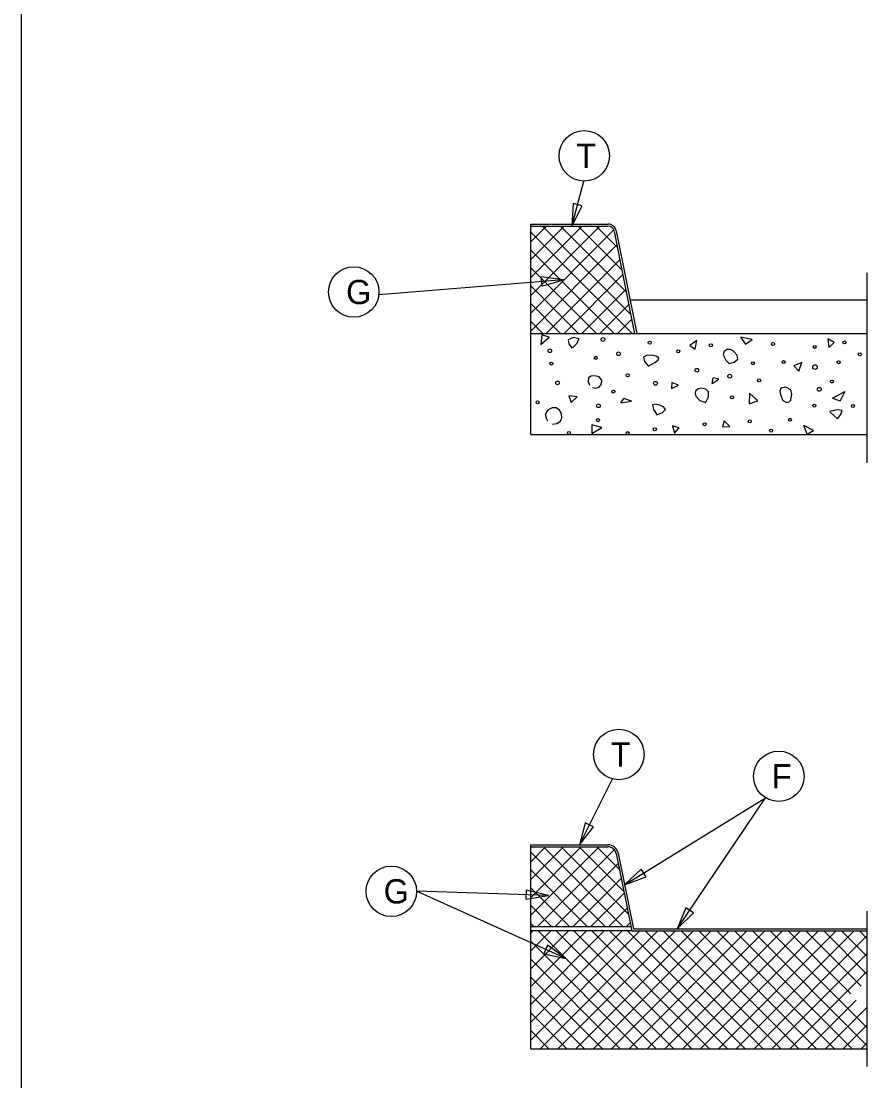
# Model space of a CAD drawing. Extents: x -439.1 to -407.9, y -458.1 to -436.2.
# Drawn here: x -439.11 to -433.87, y -452.49 to -445.93 of the extents above; entities that cross this region are included whole.
import ezdxf

# ---------------------------------------------------------------- set-up
doc = ezdxf.new("R2010")
doc.units = 0
doc.layers.add('Draft_Named_Boundary', color=7, linetype='Continuous')
doc.layers.add('Level 4', color=7, linetype='Continuous')

msp = doc.modelspace()

# ---------------------------------------------------------------- linework, layer by layer
at = {"layer": 'Draft_Named_Boundary'}
msp.add_lwpolyline([(-439.109, -458.0508), (-407.859, -458.0508), (-407.859, -437.6758), (-439.109, -437.6758)], close=True, dxfattribs=at)
at = {"layer": 'Level 4'}
for p, q in [((-435.6999, -447.1978), (-435.6238, -446.9178)), ((-435.9532, -447.6257), (-435.5253, -447.1978)), ((-435.9532, -447.5152), (-435.6358, -447.1978)), ((-435.9532, -447.4047), (-435.7463, -447.1978)), ((-435.9532, -447.2943), (-435.8567, -447.1978)), ((-435.9528, -447.1844), (-435.4753, -447.1844)), ((-435.9528, -448.4869), (-435.9528, -447.1844)), ((-435.9528, -447.1982), (-435.4753, -447.1982)), ((-435.3339, -447.7438), (-435.8799, -447.1978)), ((-435.3615, -447.6057), (-435.7694, -447.1978)), ((-435.3891, -447.4676), (-435.659, -447.1978)), ((-435.4168, -447.3295), (-435.5485, -447.1978)), ((-435.9532, -447.7362), (-435.4401, -447.2231)), ((-435.3264, -447.8618), (-435.9532, -447.2349)), ((-435.4365, -447.2294), (-435.3103, -447.8644)), ((-435.424, -447.2269), (-435.2965, -447.8619)), ((-435.9532, -447.8467), (-435.42, -447.3134)), ((-435.4368, -447.8618), (-435.9532, -447.3454)), ((-435.5473, -447.8618), (-435.9532, -447.4559)), ((-435.8579, -447.8618), (-435.4016, -447.4055)), ((-435.7474, -447.8618), (-435.3832, -447.4975)), ((-433.8703, -448.6635), (-433.8703, -447.4871)), ((-435.7502, -447.5296), (-436.8942, -447.6218)), ((-435.6578, -447.8618), (-435.9532, -447.5664)), ((-435.6369, -447.8618), (-435.3647, -447.5896)), ((-435.339, -447.6532), (-433.8703, -447.6532)), ((-435.7683, -447.8618), (-435.9532, -447.6768)), ((-435.5264, -447.8618), (-435.3463, -447.6817)), ((-435.8788, -447.8618), (-435.9532, -447.7873)), ((-435.416, -447.8618), (-435.3279, -447.7737)), ((-435.9528, -447.8619), (-433.8703, -447.8619)), ((-435.884, -447.8707), (-435.8903, -447.9294)), ((-435.8903, -447.9294), (-435.8403, -447.8844)), ((-435.8403, -447.8844), (-435.884, -447.8707)), ((-434.924, -447.9057), (-434.9678, -447.9357)), ((-434.9353, -447.9582), (-434.924, -447.9057)), ((-434.5815, -447.8982), (-434.654, -447.8844)), ((-434.654, -447.8844), (-434.624, -447.9282)), ((-434.624, -447.9282), (-434.5815, -447.8982)), ((-434.0753, -447.9169), (-434.1128, -447.8957)), ((-434.1128, -447.8957), (-434.1065, -447.9482)), ((-434.1065, -447.9482), (-434.0753, -447.9169)), ((-434.9678, -447.9357), (-434.9353, -447.9582)), ((-434.274, -448.0407), (-434.324, -448.0619)), ((-434.294, -448.0944), (-434.274, -448.0407)), ((-434.324, -448.0619), (-434.294, -448.0944)), ((-435.0803, -448.1644), (-435.0828, -448.2032)), ((-435.0828, -448.2032), (-435.039, -448.1819)), ((-435.039, -448.1819), (-435.0803, -448.1644)), ((-434.8303, -448.1719), (-434.8228, -448.1369)), ((-434.8303, -448.1719), (-434.789, -448.1457)), ((-434.789, -448.1457), (-434.8228, -448.1369)), ((-435.6653, -448.2544), (-435.7178, -448.2469)), ((-435.7178, -448.2469), (-435.7028, -448.2894)), ((-434.599, -448.2319), (-434.6015, -448.2982)), ((-434.5465, -448.2794), (-434.599, -448.2319)), ((-434.084, -448.2619), (-434.009, -448.2207)), ((-434.009, -448.2207), (-434.0365, -448.2794)), ((-435.7028, -448.2894), (-435.6653, -448.2544)), ((-435.3965, -448.2919), (-435.3765, -448.2644)), ((-435.3965, -448.2919), (-435.3303, -448.2819)), ((-435.3303, -448.2819), (-435.3765, -448.2644)), ((-434.6015, -448.2982), (-434.5465, -448.2794)), ((-434.084, -448.2619), (-434.0365, -448.2794)), ((-435.5128, -448.4444), (-435.5753, -448.4269)), ((-435.5753, -448.4269), (-435.5753, -448.4819)), ((-435.5753, -448.4819), (-435.5128, -448.4444)), ((-435.034, -448.4469), (-435.0753, -448.4332)), ((-435.0753, -448.4332), (-435.064, -448.4782)), ((-435.064, -448.4782), (-435.034, -448.4469)), ((-434.7565, -448.4032), (-434.7665, -448.4394)), ((-434.7665, -448.4394), (-434.7203, -448.4369)), ((-434.7565, -448.4032), (-434.7203, -448.4369)), ((-434.7253, -448.4357), (-434.724, -448.4357)), ((-434.2015, -448.4632), (-434.2628, -448.4307)), ((-434.2415, -448.4857), (-434.2628, -448.4307)), ((-435.9528, -448.4869), (-433.8703, -448.4869)), ((-434.2415, -448.4857), (-434.2015, -448.4632)), ((-435.652, -451.0276), (-435.4477, -450.6196)), ((-435.3723, -451.2749), (-434.499, -450.7368)), ((-435.0475, -451.5484), (-434.499, -450.7368)), ((-435.9532, -451.464), (-435.5299, -451.0406)), ((-435.9532, -451.3535), (-435.6404, -451.0406)), ((-435.9532, -451.243), (-435.7509, -451.0406)), ((-435.9532, -451.1325), (-435.8614, -451.0406)), ((-435.9528, -452.2912), (-435.9528, -451.0274)), ((-435.9528, -451.0274), (-435.4753, -451.0274)), ((-435.9528, -451.0412), (-435.4753, -451.0412)), ((-435.9142, -451.5354), (-435.4372, -451.0584)), ((-435.3805, -451.5354), (-435.8753, -451.0406)), ((-435.3493, -451.4561), (-435.7648, -451.0406)), ((-435.377, -451.318), (-435.6543, -451.0406)), ((-435.4046, -451.1799), (-435.5439, -451.0406)), ((-435.491, -451.5354), (-435.9532, -451.0732)), ((-435.424, -451.0824), (-435.3278, -451.5612)), ((-435.4115, -451.0799), (-435.3178, -451.5487)), ((-435.6015, -451.5354), (-435.9532, -451.1836)), ((-435.8037, -451.5354), (-435.4119, -451.1435)), ((-435.6932, -451.5354), (-435.3934, -451.2356)), ((-435.8437, -451.3408), (-436.6605, -451.316)), ((-435.7354, -451.7327), (-436.6605, -451.316)), ((-435.712, -451.5354), (-435.9532, -451.2941)), ((-435.5828, -451.5354), (-435.375, -451.3277)), ((-435.8224, -451.5354), (-435.9532, -451.4046)), ((-435.4723, -451.5354), (-435.3566, -451.4197)), ((-433.8703, -452.4001), (-433.8703, -451.4398)), ((-435.9329, -451.5354), (-435.9532, -451.5151)), ((-435.3618, -451.5354), (-435.3382, -451.5118)), ((-435.9532, -452.2373), (-435.2774, -451.5615)), ((-435.9532, -452.1269), (-435.3878, -451.5615)), ((-435.9532, -452.0164), (-435.4983, -451.5615)), ((-435.9532, -451.9059), (-435.6088, -451.5615)), ((-435.9532, -451.7954), (-435.7193, -451.5615)), ((-435.9532, -451.6849), (-435.8298, -451.5615)), ((-435.9532, -451.5745), (-435.9402, -451.5615)), ((-435.334, -451.5349), (-435.9528, -451.5349)), ((-435.3278, -451.5612), (-435.9528, -451.5612)), ((-435.1777, -452.2906), (-435.9069, -451.5615)), ((-435.896, -452.2906), (-435.1669, -451.5615)), ((-435.0673, -452.2906), (-435.7964, -451.5615)), ((-435.7855, -452.2906), (-435.0564, -451.5615)), ((-434.9568, -452.2906), (-435.6859, -451.5615)), ((-435.6751, -452.2906), (-434.9459, -451.5615)), ((-434.8463, -452.2906), (-435.5754, -451.5615)), ((-435.5646, -452.2906), (-434.8354, -451.5615)), ((-434.7358, -452.2906), (-435.465, -451.5615)), ((-435.4541, -452.2906), (-434.725, -451.5615)), ((-434.6253, -452.2906), (-435.3545, -451.5615)), ((-435.3436, -452.2906), (-434.6145, -451.5615)), ((-435.3278, -451.5612), (-433.8703, -451.5612)), ((-435.3178, -451.5487), (-433.8703, -451.5487)), ((-434.5149, -452.2906), (-435.244, -451.5615)), ((-435.2331, -452.2906), (-434.504, -451.5615)), ((-434.4044, -452.2906), (-435.1335, -451.5615)), ((-435.1227, -452.2906), (-434.3935, -451.5615)), ((-434.2939, -452.2906), (-435.023, -451.5615)), ((-435.0122, -452.2906), (-434.283, -451.5615)), ((-434.1834, -452.2906), (-434.9125, -451.5615)), ((-434.9017, -452.2906), (-434.1725, -451.5615)), ((-434.0729, -452.2906), (-434.8021, -451.5615)), ((-434.7912, -452.2906), (-434.0621, -451.5615)), ((-433.9625, -452.2906), (-434.6916, -451.5615)), ((-434.6807, -452.2906), (-433.9516, -451.5615)), ((-433.87, -452.2726), (-434.5811, -451.5615)), ((-434.5702, -452.2906), (-433.87, -451.5903)), ((-433.87, -452.1621), (-434.4706, -451.5615)), ((-433.9711, -451.9505), (-434.3602, -451.5615)), ((-433.9075, -451.9036), (-434.2497, -451.5615)), ((-433.8703, -451.8304), (-434.1392, -451.5615)), ((-433.87, -451.7202), (-434.0287, -451.5615)), ((-433.87, -451.6097), (-433.9182, -451.5615)), ((-435.2882, -452.2906), (-435.9532, -451.6256)), ((-434.4598, -452.2906), (-433.87, -451.7008)), ((-435.3987, -452.2906), (-435.9532, -451.7361)), ((-435.5092, -452.2906), (-435.9532, -451.8465)), ((-434.3493, -452.2906), (-433.87, -451.8113)), ((-435.6197, -452.2906), (-435.9532, -451.957)), ((-434.2388, -452.2906), (-433.9388, -451.9906)), ((-434.1283, -452.2906), (-433.87, -452.0323)), ((-435.7302, -452.2906), (-435.9532, -452.0675)), ((-435.8406, -452.2906), (-435.9532, -452.178)), ((-434.0178, -452.2906), (-433.87, -452.1427)), ((-435.9511, -452.2906), (-435.9532, -452.2885)), ((-435.9528, -452.2912), (-433.8703, -452.2912)), ((-433.9074, -452.2906), (-433.87, -452.2532))]:
    msp.add_line(p, q, dxfattribs=at)
for points in [[(-435.6913, -447.0568), (-435.6999, -447.1978), (-435.6359, -447.0718)], [(-435.8858, -447.5693), (-435.7502, -447.5296), (-435.8904, -447.5121)], [(-435.6157, -450.8911), (-435.652, -451.0276), (-435.5644, -450.9168)], [(-435.2696, -451.1779), (-435.3723, -451.2749), (-435.2395, -451.2268)], [(-435.9829, -451.3653), (-435.8437, -451.3408), (-435.9811, -451.3079)], [(-434.9939, -451.4178), (-435.0475, -451.5484), (-434.9463, -451.4499)], [(-435.8732, -451.7021), (-435.7354, -451.7327), (-435.8497, -451.6497)]]:
    msp.add_lwpolyline(points, close=True, dxfattribs=at)
for points in [[(-435.6956, -447.95), (-435.6657, -447.9208), (-435.6554, -447.8941), (-435.6882, -447.8874), (-435.7213, -447.9017), (-435.7171, -447.9268), (-435.6981, -447.9525)], [(-434.7266, -448.0473), (-434.6936, -448.0395), (-434.6714, -448.0215), (-434.6759, -447.9962), (-434.6971, -447.972), (-434.717, -447.9613), (-434.7379, -447.9619), (-434.755, -447.9738), (-434.7618, -447.9914), (-434.7604, -447.9971), (-434.758, -448.0027), (-434.7444, -448.0265), (-434.7266, -448.0466)], [(-435.2262, -448.0642), (-435.1812, -448.0392), (-435.1638, -448.0253), (-435.1596, -448.0127), (-435.1763, -448.0019), (-435.2064, -447.9965), (-435.237, -447.9983), (-435.255, -448.009), (-435.2481, -448.0351), (-435.2268, -448.0629)], [(-435.5707, -448.1972), (-435.5496, -448.1995), (-435.5299, -448.1935), (-435.5152, -448.174), (-435.5136, -448.1502), (-435.5299, -448.131), (-435.5575, -448.1232), (-435.5798, -448.1259), (-435.5952, -448.137), (-435.5979, -448.1592), (-435.5901, -448.1828)], [(-434.8684, -448.2864), (-434.8529, -448.2548), (-434.8534, -448.223), (-434.8694, -448.2075), (-434.8935, -448.201), (-434.9167, -448.2047), (-434.9325, -448.218), (-434.9353, -448.2335), (-434.9312, -448.25), (-434.9055, -448.2766), (-434.8697, -448.2882)], [(-434.3425, -448.27), (-434.3357, -448.2394), (-434.3432, -448.2111), (-434.3738, -448.195), (-434.404, -448.2004), (-434.4106, -448.2174), (-434.4078, -448.2405), (-434.3923, -448.2759), (-434.3676, -448.2901), (-434.3537, -448.2841), (-434.3413, -448.2732)], [(-435.169, -448.3635), (-435.1374, -448.3504), (-435.1195, -448.3328), (-435.1302, -448.3184), (-435.1549, -448.3062), (-435.1819, -448.2999), (-435.1998, -448.3033), (-435.1942, -448.3317), (-435.1709, -448.3667)], [(-435.8182, -448.4237), (-435.7916, -448.4191), (-435.7699, -448.4049), (-435.7609, -448.3832), (-435.763, -448.3584), (-435.776, -448.3359), (-435.7969, -448.3227), (-435.8218, -448.3227), (-435.8452, -448.3346), (-435.8568, -448.3475), (-435.8627, -448.3628), (-435.8601, -448.3831), (-435.8496, -448.4019)], [(-434.0533, -448.3907), (-434.0326, -448.3635), (-434.0252, -448.3396), (-434.0568, -448.3338), (-434.1024, -448.3446)], [(-434.0987, -448.3484), (-434.076, -448.3696), (-434.0533, -448.3907)]]:
    msp.add_lwpolyline(points, dxfattribs=at)
for centre, radius in [((-435.6222, -446.7617), 0.1562), ((-437.0495, -447.6051), 0.1562), ((-435.506, -447.8992), 0.0115), ((-435.2167, -447.9186), 0.00937), ((-434.4536, -447.9274), 0.00937), ((-434.0112, -447.9174), 0.00937), ((-435.8349, -447.9688), 0.0115), ((-435.4094, -447.9876), 0.0115), ((-435.0404, -447.972), 0.00937), ((-434.8383, -447.9349), 0.00937), ((-434.1944, -447.945), 0.00937), ((-433.9157, -447.9909), 0.00937), ((-435.8261, -448.0479), 0.00937), ((-435.5506, -448.0127), 0.00937), ((-434.5779, -448.0458), 0.00937), ((-434.3877, -448.0391), 0.00937), ((-434.047, -448.0397), 0.00937), ((-435.3529, -448.1207), 0.00937), ((-434.9249, -448.0893), 0.0115), ((-434.7214, -448.1261), 0.0115), ((-434.1932, -448.0699), 0.0141), ((-435.7872, -448.1678), 0.0115), ((-435.181, -448.1703), 0.0115), ((-434.539, -448.1521), 0.00937), ((-434.0887, -448.1597), 0.00937), ((-435.442, -448.2212), 0.00937), ((-434.7065, -448.2575), 0.00937), ((-434.1665, -448.2074), 0.0115), ((-435.9115, -448.2882), 0.00937), ((-435.5343, -448.3092), 0.0115), ((-434.1976, -448.3083), 0.00937), ((-433.9585, -448.3108), 0.00937), ((-435.537, -448.3986), 0.00937), ((-435.185, -448.4551), 0.00937), ((-434.8762, -448.4237), 0.00937), ((-434.5973, -448.4062), 0.00937), ((-434.3488, -448.3962), 0.00937), ((-435.7171, -448.4783), 0.00937), ((-435.3538, -448.4789), 0.00937), ((-434.4652, -448.4632), 0.00937), ((-435.408, -450.4685), 0.1562), ((-434.4174, -450.6036), 0.1562), ((-436.8168, -451.316), 0.1562)]:
    msp.add_circle(centre, radius, dxfattribs=at)
for centre, radius in [((-435.4751, -447.2368), 0.0521), ((-435.4751, -447.2368), 0.0391), ((-435.4751, -451.0927), 0.0651), ((-435.4751, -451.0927), 0.0521)]:
    msp.add_arc(centre, radius, 11.30993, 90, dxfattribs=at)

# ---------------------------------------------------------------- texts
for s, p in [('T', (-435.6722, -446.8367)), ('G', (-437.097, -447.68)), ('T', (-435.4579, -450.5435)), ('F', (-434.4611, -450.6786)), ('G', (-436.8642, -451.391))]:
    msp.add_text(s, height=0.15, dxfattribs=at).set_placement(p)

doc.saveas('drawing.dxf')
